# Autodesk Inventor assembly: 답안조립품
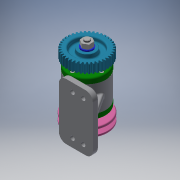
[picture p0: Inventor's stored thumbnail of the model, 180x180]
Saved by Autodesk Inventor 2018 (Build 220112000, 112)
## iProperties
Created: 2023-08
Part Number: 답안조립품
Material: 일반
Document SubType Name: Assembly
Designer: home
Author: home
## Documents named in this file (12)
- C:\Users\home\Desktop\730806V1004\답안조립품.iam
- C:\Users\home\Desktop\730806V1004\본체.ipt
- C:\Users\home\Desktop\730806V1004\베어링 6204.ipt
- C:\Users\home\Desktop\730806V1004\축.ipt
- C:\Users\home\Desktop\730806V1004\커버.ipt
- C:\Users\home\Desktop\730806V1004\오일실 20x35x8.ipt
- C:\Users\home\Desktop\730806V1004\볼트 M4 x 12.ipt
- C:\Users\home\Desktop\730806V1004\키 5x5.ipt
- C:\Users\home\Desktop\730806V1004\V벨트풀리.ipt
- C:\Users\home\Desktop\730806V1004\스퍼기어.ipt
- C:\Users\home\Desktop\730806V1004\와셔 12x24.ipt
- C:\Users\home\Desktop\730806V1004\너트 M12x1.25.ipt
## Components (1 placed, 1 different names)
1. V벨트풀리:1
